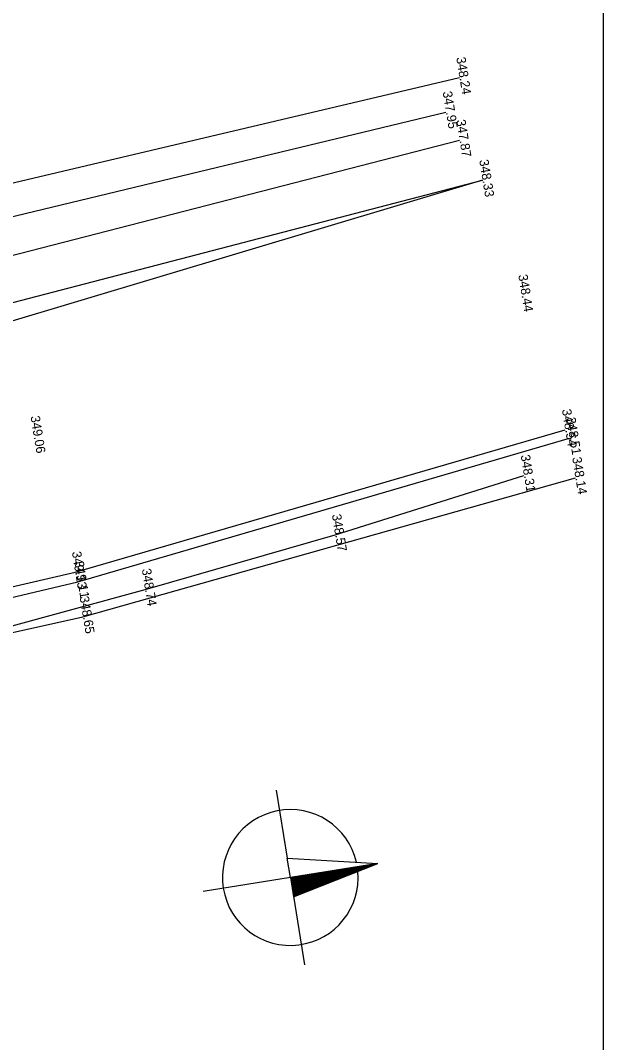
# Model space of a CAD drawing. Extents: x -600096 to -597522, y -1151695 to -1149849.
# Drawn here: x -599530.19 to -599518.4, y -1151599.7 to -1151579.02 of the extents above; entities that cross this region are included whole.
import ezdxf

# ---------------------------------------------------------------- set-up
doc = ezdxf.new("R2010")
doc.units = 0
for name, color, linetype in [('Hrana komunikace', 7, 'Continuous'), ('MPPV_Dno_prikopu', 7, 'Continuous'), ('MPPV_komunikace', 7, 'Continuous'), ('MPPV_svah', 7, 'Continuous'), ('Ram03', 7, 'Continuous'), ('rám', 7, 'Continuous'), ('Svodidla', 7, 'Continuous'), ('Tabulka', 7, 'Continuous'), ('Vrstva 12', 7, 'Continuous')]:
    doc.layers.add(name, color=color, linetype=linetype)

msp = doc.modelspace()

# ---------------------------------------------------------------- linework, layer by layer
at = {"layer": 'Hrana komunikace'}
for p, q in [((-599530.786, -1151584.848), (-599520.851, -1151582.258)), ((-599529.035, -1151590.381), (-599519.09, -1151587.475)), ((-599539.165, -1151592.769), (-599529.035, -1151590.381))]:
    msp.add_line(p, q, dxfattribs=at)
at = {"layer": 'MPPV_Dno_prikopu'}
for p, q in [((-599531.447, -1151583.253), (-599521.589, -1151580.878)), ((-599521.315, -1151581.452), (-599531.157, -1151583.986))]:
    msp.add_line(p, q, dxfattribs=at)
at = {"layer": 'MPPV_komunikace'}
for p, q in [((-599520.851, -1151582.258), (-599530.64, -1151585.189)), ((-599529.087, -1151590.186), (-599519.178, -1151587.307)), ((-599539.234, -1151592.527), (-599529.087, -1151590.186))]:
    msp.add_line(p, q, dxfattribs=at)
at = {"layer": 'MPPV_svah'}
for p, q in [((-599521.316, -1151580.186), (-599531.269, -1151582.536)), ((-599528.931, -1151591.093), (-599518.972, -1151588.277)), ((-599541.399, -1151593.867), (-599528.931, -1151591.093))]:
    msp.add_line(p, q, dxfattribs=at)
at = {"layer": 'Ram03'}
msp.add_line((-599518.403, -1151620.382), (-599518.403, -1151471.882), dxfattribs=at)
msp.add_line((-599518.403, -1151620.382), (-599518.403, -1151471.882), dxfattribs=at)
at = {"layer": 'rám'}
for p, q in [((-599523.557, -1151596.174), (-599523.55, -1151596.311)), ((-599523.552, -1151596.174), (-599523.545, -1151596.309)), ((-599523.547, -1151596.173), (-599523.54, -1151596.307)), ((-599523.542, -1151596.172), (-599523.536, -1151596.305)), ((-599523.537, -1151596.171), (-599523.531, -1151596.303)), ((-599523.532, -1151596.17), (-599523.526, -1151596.301)), ((-599523.527, -1151596.17), (-599523.521, -1151596.299)), ((-599523.522, -1151596.169), (-599523.516, -1151596.297)), ((-599523.517, -1151596.168), (-599523.511, -1151596.295)), ((-599523.512, -1151596.167), (-599523.506, -1151596.293)), ((-599523.507, -1151596.166), (-599523.501, -1151596.291)), ((-599523.502, -1151596.166), (-599523.496, -1151596.289)), ((-599523.497, -1151596.165), (-599523.491, -1151596.287)), ((-599523.492, -1151596.164), (-599523.486, -1151596.285)), ((-599523.487, -1151596.163), (-599523.482, -1151596.283)), ((-599523.482, -1151596.162), (-599523.477, -1151596.281)), ((-599523.477, -1151596.162), (-599523.472, -1151596.279)), ((-599523.472, -1151596.161), (-599523.467, -1151596.277)), ((-599523.467, -1151596.16), (-599523.462, -1151596.275)), ((-599523.462, -1151596.159), (-599523.457, -1151596.274)), ((-599523.457, -1151596.158), (-599523.452, -1151596.272)), ((-599523.452, -1151596.158), (-599523.447, -1151596.27)), ((-599523.447, -1151596.157), (-599523.442, -1151596.268)), ((-599523.442, -1151596.156), (-599523.437, -1151596.266)), ((-599523.437, -1151596.155), (-599523.432, -1151596.264)), ((-599523.432, -1151596.154), (-599523.427, -1151596.262)), ((-599523.428, -1151596.154), (-599523.423, -1151596.26)), ((-599523.423, -1151596.153), (-599523.418, -1151596.258)), ((-599523.418, -1151596.152), (-599523.413, -1151596.256)), ((-599523.413, -1151596.151), (-599523.408, -1151596.254)), ((-599523.408, -1151596.15), (-599523.403, -1151596.252)), ((-599523.403, -1151596.15), (-599523.398, -1151596.25)), ((-599523.398, -1151596.149), (-599523.393, -1151596.248)), ((-599523.393, -1151596.148), (-599523.388, -1151596.246)), ((-599523.388, -1151596.147), (-599523.383, -1151596.244)), ((-599523.383, -1151596.146), (-599523.378, -1151596.242)), ((-599523.378, -1151596.146), (-599523.373, -1151596.24)), ((-599523.373, -1151596.145), (-599523.368, -1151596.238)), ((-599523.368, -1151596.144), (-599523.364, -1151596.237)), ((-599523.363, -1151596.143), (-599523.359, -1151596.235)), ((-599523.358, -1151596.142), (-599523.354, -1151596.233)), ((-599523.353, -1151596.142), (-599523.349, -1151596.231)), ((-599523.348, -1151596.141), (-599523.344, -1151596.229)), ((-599523.343, -1151596.14), (-599523.339, -1151596.227)), ((-599523.338, -1151596.139), (-599523.334, -1151596.225)), ((-599523.333, -1151596.138), (-599523.329, -1151596.223)), ((-599523.328, -1151596.138), (-599523.324, -1151596.221)), ((-599523.323, -1151596.137), (-599523.319, -1151596.219)), ((-599523.318, -1151596.136), (-599523.314, -1151596.217)), ((-599523.313, -1151596.135), (-599523.31, -1151596.215)), ((-599523.308, -1151596.134), (-599523.305, -1151596.213)), ((-599523.303, -1151596.134), (-599523.3, -1151596.211)), ((-599523.298, -1151596.133), (-599523.295, -1151596.209)), ((-599523.293, -1151596.132), (-599523.29, -1151596.207)), ((-599523.288, -1151596.131), (-599523.285, -1151596.205)), ((-599523.283, -1151596.13), (-599523.28, -1151596.203)), ((-599523.278, -1151596.13), (-599523.275, -1151596.201)), ((-599523.274, -1151596.129), (-599523.27, -1151596.199)), ((-599523.269, -1151596.128), (-599523.265, -1151596.198)), ((-599523.264, -1151596.127), (-599523.26, -1151596.196)), ((-599523.259, -1151596.126), (-599523.255, -1151596.194)), ((-599523.254, -1151596.126), (-599523.251, -1151596.192)), ((-599523.249, -1151596.125), (-599523.246, -1151596.19)), ((-599523.244, -1151596.124), (-599523.241, -1151596.188)), ((-599523.239, -1151596.123), (-599523.236, -1151596.186)), ((-599523.234, -1151596.123), (-599523.231, -1151596.184)), ((-599523.229, -1151596.122), (-599523.226, -1151596.182)), ((-599523.224, -1151596.121), (-599523.221, -1151596.18)), ((-599523.219, -1151596.12), (-599523.216, -1151596.178)), ((-599523.214, -1151596.119), (-599523.211, -1151596.176)), ((-599523.209, -1151596.119), (-599523.206, -1151596.174)), ((-599523.204, -1151596.118), (-599523.201, -1151596.172)), ((-599523.199, -1151596.117), (-599523.196, -1151596.17)), ((-599523.194, -1151596.116), (-599523.192, -1151596.168)), ((-599523.189, -1151596.115), (-599523.187, -1151596.166)), ((-599523.184, -1151596.115), (-599523.182, -1151596.164)), ((-599523.179, -1151596.114), (-599523.177, -1151596.162)), ((-599523.174, -1151596.113), (-599523.172, -1151596.161)), ((-599523.169, -1151596.112), (-599523.167, -1151596.159)), ((-599523.164, -1151596.111), (-599523.162, -1151596.157)), ((-599523.159, -1151596.111), (-599523.157, -1151596.155)), ((-599523.154, -1151596.11), (-599523.152, -1151596.153)), ((-599523.149, -1151596.109), (-599523.147, -1151596.151)), ((-599523.144, -1151596.108), (-599523.142, -1151596.149)), ((-599523.139, -1151596.107), (-599523.138, -1151596.147)), ((-599523.134, -1151596.107), (-599523.133, -1151596.145)), ((-599523.129, -1151596.106), (-599523.128, -1151596.143)), ((-599523.124, -1151596.105), (-599523.123, -1151596.141)), ((-599523.12, -1151596.104), (-599523.118, -1151596.139)), ((-599523.115, -1151596.103), (-599523.113, -1151596.137)), ((-599523.11, -1151596.103), (-599523.108, -1151596.135)), ((-599523.105, -1151596.102), (-599523.103, -1151596.133)), ((-599523.1, -1151596.101), (-599523.098, -1151596.131)), ((-599523.095, -1151596.1), (-599523.093, -1151596.129)), ((-599523.09, -1151596.099), (-599523.088, -1151596.127)), ((-599523.085, -1151596.099), (-599523.083, -1151596.125)), ((-599523.08, -1151596.098), (-599523.079, -1151596.123)), ((-599523.075, -1151596.097), (-599523.074, -1151596.122)), ((-599523.07, -1151596.096), (-599523.069, -1151596.12)), ((-599523.065, -1151596.095), (-599523.064, -1151596.118)), ((-599523.06, -1151596.095), (-599523.059, -1151596.116)), ((-599523.055, -1151596.094), (-599523.054, -1151596.114)), ((-599523.05, -1151596.093), (-599523.049, -1151596.112)), ((-599523.045, -1151596.092), (-599523.044, -1151596.11)), ((-599523.04, -1151596.091), (-599523.039, -1151596.108)), ((-599523.035, -1151596.091), (-599523.034, -1151596.106)), ((-599523.03, -1151596.09), (-599523.029, -1151596.104)), ((-599523.025, -1151596.089), (-599523.025, -1151596.102)), ((-599523.02, -1151596.088), (-599523.02, -1151596.1)), ((-599523.015, -1151596.087), (-599523.015, -1151596.098)), ((-599523.01, -1151596.087), (-599523.01, -1151596.096)), ((-599523.005, -1151596.086), (-599523.005, -1151596.094)), ((-599523, -1151596.085), (-599523, -1151596.092)), ((-599522.995, -1151596.084), (-599522.995, -1151596.09)), ((-599522.99, -1151596.083), (-599522.99, -1151596.088)), ((-599522.985, -1151596.083), (-599522.985, -1151596.086)), ((-599522.98, -1151596.082), (-599522.98, -1151596.085)), ((-599522.975, -1151596.081), (-599522.975, -1151596.083)), ((-599522.97, -1151596.08), (-599522.97, -1151596.081)), ((-599524.734, -1151596.364), (-599524.734, -1151596.375)), ((-599524.729, -1151596.363), (-599524.727, -1151596.419)), ((-599524.724, -1151596.362), (-599524.719, -1151596.462)), ((-599524.719, -1151596.361), (-599524.712, -1151596.505)), ((-599524.714, -1151596.361), (-599524.705, -1151596.548)), ((-599524.709, -1151596.36), (-599524.698, -1151596.591)), ((-599524.704, -1151596.359), (-599524.691, -1151596.634)), ((-599524.699, -1151596.358), (-599524.684, -1151596.678)), ((-599524.694, -1151596.357), (-599524.677, -1151596.721)), ((-599524.689, -1151596.357), (-599524.671, -1151596.755)), ((-599524.684, -1151596.356), (-599524.666, -1151596.753)), ((-599524.679, -1151596.355), (-599524.661, -1151596.751)), ((-599524.674, -1151596.354), (-599524.656, -1151596.749)), ((-599524.67, -1151596.353), (-599524.651, -1151596.747)), ((-599524.665, -1151596.353), (-599524.646, -1151596.745)), ((-599524.66, -1151596.352), (-599524.641, -1151596.743)), ((-599524.655, -1151596.351), (-599524.636, -1151596.741)), ((-599524.65, -1151596.35), (-599524.631, -1151596.739)), ((-599524.645, -1151596.349), (-599524.626, -1151596.737)), ((-599524.64, -1151596.349), (-599524.622, -1151596.735)), ((-599524.635, -1151596.348), (-599524.617, -1151596.733)), ((-599524.63, -1151596.347), (-599524.612, -1151596.731)), ((-599524.625, -1151596.346), (-599524.607, -1151596.73)), ((-599524.62, -1151596.345), (-599524.602, -1151596.728)), ((-599524.615, -1151596.345), (-599524.597, -1151596.726)), ((-599524.61, -1151596.344), (-599524.592, -1151596.724)), ((-599524.605, -1151596.343), (-599524.587, -1151596.722)), ((-599524.6, -1151596.342), (-599524.582, -1151596.72)), ((-599524.595, -1151596.341), (-599524.577, -1151596.718)), ((-599524.59, -1151596.341), (-599524.572, -1151596.716)), ((-599524.585, -1151596.34), (-599524.568, -1151596.714)), ((-599524.58, -1151596.339), (-599524.563, -1151596.712)), ((-599524.575, -1151596.338), (-599524.558, -1151596.71)), ((-599524.57, -1151596.337), (-599524.553, -1151596.708)), ((-599524.565, -1151596.337), (-599524.548, -1151596.706)), ((-599524.56, -1151596.336), (-599524.543, -1151596.704)), ((-599524.555, -1151596.335), (-599524.538, -1151596.702)), ((-599524.55, -1151596.334), (-599524.533, -1151596.7)), ((-599524.545, -1151596.333), (-599524.528, -1151596.698)), ((-599524.54, -1151596.333), (-599524.523, -1151596.696)), ((-599524.535, -1151596.332), (-599524.518, -1151596.694)), ((-599524.53, -1151596.331), (-599524.513, -1151596.693)), ((-599524.525, -1151596.33), (-599524.509, -1151596.691)), ((-599524.52, -1151596.329), (-599524.504, -1151596.689)), ((-599524.516, -1151596.329), (-599524.499, -1151596.687)), ((-599524.511, -1151596.328), (-599524.494, -1151596.685)), ((-599524.506, -1151596.327), (-599524.489, -1151596.683)), ((-599524.501, -1151596.326), (-599524.484, -1151596.681)), ((-599524.496, -1151596.325), (-599524.479, -1151596.679)), ((-599524.491, -1151596.325), (-599524.474, -1151596.677)), ((-599524.486, -1151596.324), (-599524.469, -1151596.675)), ((-599524.481, -1151596.323), (-599524.464, -1151596.673)), ((-599524.476, -1151596.322), (-599524.459, -1151596.671)), ((-599524.471, -1151596.321), (-599524.454, -1151596.669)), ((-599524.466, -1151596.321), (-599524.45, -1151596.667)), ((-599524.461, -1151596.32), (-599524.445, -1151596.665)), ((-599524.456, -1151596.319), (-599524.44, -1151596.663)), ((-599524.451, -1151596.318), (-599524.435, -1151596.661)), ((-599524.446, -1151596.317), (-599524.43, -1151596.659)), ((-599524.441, -1151596.317), (-599524.425, -1151596.657)), ((-599524.436, -1151596.316), (-599524.42, -1151596.655)), ((-599524.431, -1151596.315), (-599524.415, -1151596.654)), ((-599524.426, -1151596.314), (-599524.41, -1151596.652)), ((-599524.421, -1151596.313), (-599524.405, -1151596.65)), ((-599524.416, -1151596.313), (-599524.4, -1151596.648)), ((-599524.411, -1151596.312), (-599524.396, -1151596.646)), ((-599524.406, -1151596.311), (-599524.391, -1151596.644)), ((-599524.401, -1151596.31), (-599524.386, -1151596.642)), ((-599524.396, -1151596.309), (-599524.381, -1151596.64)), ((-599524.391, -1151596.309), (-599524.376, -1151596.638)), ((-599524.386, -1151596.308), (-599524.371, -1151596.636)), ((-599524.381, -1151596.307), (-599524.366, -1151596.634)), ((-599524.376, -1151596.306), (-599524.361, -1151596.632)), ((-599524.371, -1151596.305), (-599524.356, -1151596.63)), ((-599524.366, -1151596.305), (-599524.351, -1151596.628)), ((-599524.362, -1151596.304), (-599524.346, -1151596.626)), ((-599524.357, -1151596.303), (-599524.341, -1151596.624)), ((-599524.352, -1151596.302), (-599524.337, -1151596.622)), ((-599524.347, -1151596.301), (-599524.332, -1151596.62)), ((-599524.342, -1151596.301), (-599524.327, -1151596.618)), ((-599524.337, -1151596.3), (-599524.322, -1151596.617)), ((-599524.332, -1151596.299), (-599524.317, -1151596.615)), ((-599524.327, -1151596.298), (-599524.312, -1151596.613)), ((-599524.322, -1151596.297), (-599524.307, -1151596.611)), ((-599524.317, -1151596.297), (-599524.302, -1151596.609)), ((-599524.312, -1151596.296), (-599524.297, -1151596.607)), ((-599524.307, -1151596.295), (-599524.292, -1151596.605)), ((-599524.302, -1151596.294), (-599524.287, -1151596.603)), ((-599524.297, -1151596.293), (-599524.282, -1151596.601)), ((-599524.292, -1151596.293), (-599524.278, -1151596.599)), ((-599524.287, -1151596.292), (-599524.273, -1151596.597)), ((-599524.282, -1151596.291), (-599524.268, -1151596.595)), ((-599524.277, -1151596.29), (-599524.263, -1151596.593)), ((-599524.272, -1151596.289), (-599524.258, -1151596.591)), ((-599524.267, -1151596.289), (-599524.253, -1151596.589)), ((-599524.262, -1151596.288), (-599524.248, -1151596.587)), ((-599524.257, -1151596.287), (-599524.243, -1151596.585)), ((-599524.252, -1151596.286), (-599524.238, -1151596.583)), ((-599524.247, -1151596.285), (-599524.233, -1151596.581)), ((-599524.242, -1151596.285), (-599524.228, -1151596.579)), ((-599524.237, -1151596.284), (-599524.224, -1151596.578)), ((-599524.232, -1151596.283), (-599524.219, -1151596.576)), ((-599524.227, -1151596.282), (-599524.214, -1151596.574)), ((-599524.222, -1151596.281), (-599524.209, -1151596.572)), ((-599524.217, -1151596.281), (-599524.204, -1151596.57)), ((-599524.212, -1151596.28), (-599524.199, -1151596.568)), ((-599524.208, -1151596.279), (-599524.194, -1151596.566)), ((-599524.203, -1151596.278), (-599524.189, -1151596.564)), ((-599524.198, -1151596.277), (-599524.184, -1151596.562)), ((-599524.193, -1151596.277), (-599524.179, -1151596.56)), ((-599524.188, -1151596.276), (-599524.174, -1151596.558)), ((-599524.183, -1151596.275), (-599524.169, -1151596.556)), ((-599524.178, -1151596.274), (-599524.165, -1151596.554)), ((-599524.173, -1151596.273), (-599524.16, -1151596.552)), ((-599524.168, -1151596.273), (-599524.155, -1151596.55)), ((-599524.163, -1151596.272), (-599524.15, -1151596.548)), ((-599524.158, -1151596.271), (-599524.145, -1151596.546)), ((-599524.153, -1151596.27), (-599524.14, -1151596.544)), ((-599524.148, -1151596.269), (-599524.135, -1151596.542)), ((-599524.143, -1151596.269), (-599524.13, -1151596.541)), ((-599524.138, -1151596.268), (-599524.125, -1151596.539)), ((-599524.133, -1151596.267), (-599524.12, -1151596.537)), ((-599524.128, -1151596.266), (-599524.115, -1151596.535)), ((-599524.123, -1151596.265), (-599524.11, -1151596.533)), ((-599524.118, -1151596.265), (-599524.106, -1151596.531)), ((-599524.113, -1151596.264), (-599524.101, -1151596.529)), ((-599524.108, -1151596.263), (-599524.096, -1151596.527)), ((-599524.103, -1151596.262), (-599524.091, -1151596.525)), ((-599524.098, -1151596.261), (-599524.086, -1151596.523)), ((-599524.093, -1151596.261), (-599524.081, -1151596.521)), ((-599524.088, -1151596.26), (-599524.076, -1151596.519)), ((-599524.083, -1151596.259), (-599524.071, -1151596.517)), ((-599524.078, -1151596.258), (-599524.066, -1151596.515)), ((-599524.073, -1151596.257), (-599524.061, -1151596.513)), ((-599524.068, -1151596.257), (-599524.056, -1151596.511)), ((-599524.063, -1151596.256), (-599524.052, -1151596.509)), ((-599524.058, -1151596.255), (-599524.047, -1151596.507)), ((-599524.053, -1151596.254), (-599524.042, -1151596.505)), ((-599524.049, -1151596.253), (-599524.037, -1151596.503)), ((-599524.044, -1151596.253), (-599524.032, -1151596.502)), ((-599524.039, -1151596.252), (-599524.027, -1151596.5)), ((-599524.034, -1151596.251), (-599524.022, -1151596.498)), ((-599524.029, -1151596.25), (-599524.017, -1151596.496)), ((-599524.024, -1151596.249), (-599524.012, -1151596.494)), ((-599524.019, -1151596.249), (-599524.007, -1151596.492)), ((-599524.014, -1151596.248), (-599524.002, -1151596.49)), ((-599524.009, -1151596.247), (-599523.997, -1151596.488)), ((-599524.004, -1151596.246), (-599523.993, -1151596.486)), ((-599523.999, -1151596.246), (-599523.988, -1151596.484)), ((-599523.994, -1151596.245), (-599523.983, -1151596.482)), ((-599523.989, -1151596.244), (-599523.978, -1151596.48)), ((-599523.984, -1151596.243), (-599523.973, -1151596.478)), ((-599523.979, -1151596.242), (-599523.968, -1151596.476)), ((-599523.974, -1151596.242), (-599523.963, -1151596.474)), ((-599523.969, -1151596.241), (-599523.958, -1151596.472)), ((-599523.964, -1151596.24), (-599523.953, -1151596.47)), ((-599523.959, -1151596.239), (-599523.948, -1151596.468)), ((-599523.954, -1151596.238), (-599523.943, -1151596.466)), ((-599523.949, -1151596.238), (-599523.939, -1151596.465)), ((-599523.944, -1151596.237), (-599523.934, -1151596.463)), ((-599523.939, -1151596.236), (-599523.929, -1151596.461)), ((-599523.934, -1151596.235), (-599523.924, -1151596.459)), ((-599523.929, -1151596.234), (-599523.919, -1151596.457)), ((-599523.924, -1151596.234), (-599523.914, -1151596.455)), ((-599523.919, -1151596.233), (-599523.909, -1151596.453)), ((-599523.914, -1151596.232), (-599523.904, -1151596.451)), ((-599523.909, -1151596.231), (-599523.899, -1151596.449)), ((-599523.904, -1151596.23), (-599523.894, -1151596.447)), ((-599523.899, -1151596.23), (-599523.889, -1151596.445)), ((-599523.895, -1151596.229), (-599523.884, -1151596.443)), ((-599523.89, -1151596.228), (-599523.88, -1151596.441)), ((-599523.885, -1151596.227), (-599523.875, -1151596.439)), ((-599523.88, -1151596.226), (-599523.87, -1151596.437)), ((-599523.875, -1151596.226), (-599523.865, -1151596.435)), ((-599523.87, -1151596.225), (-599523.86, -1151596.433)), ((-599523.865, -1151596.224), (-599523.855, -1151596.431)), ((-599523.86, -1151596.223), (-599523.85, -1151596.429)), ((-599523.855, -1151596.222), (-599523.845, -1151596.427)), ((-599523.85, -1151596.222), (-599523.84, -1151596.426)), ((-599523.845, -1151596.221), (-599523.835, -1151596.424)), ((-599523.84, -1151596.22), (-599523.83, -1151596.422)), ((-599523.835, -1151596.219), (-599523.825, -1151596.42)), ((-599523.83, -1151596.218), (-599523.821, -1151596.418)), ((-599523.825, -1151596.218), (-599523.816, -1151596.416)), ((-599523.82, -1151596.217), (-599523.811, -1151596.414)), ((-599523.815, -1151596.216), (-599523.806, -1151596.412)), ((-599523.81, -1151596.215), (-599523.801, -1151596.41)), ((-599523.805, -1151596.214), (-599523.796, -1151596.408)), ((-599523.8, -1151596.214), (-599523.791, -1151596.406)), ((-599523.795, -1151596.213), (-599523.786, -1151596.404)), ((-599523.79, -1151596.212), (-599523.781, -1151596.402)), ((-599523.785, -1151596.211), (-599523.776, -1151596.4)), ((-599523.78, -1151596.21), (-599523.771, -1151596.398)), ((-599523.775, -1151596.21), (-599523.767, -1151596.396)), ((-599523.77, -1151596.209), (-599523.762, -1151596.394)), ((-599523.765, -1151596.208), (-599523.757, -1151596.392)), ((-599523.76, -1151596.207), (-599523.752, -1151596.39)), ((-599523.755, -1151596.206), (-599523.747, -1151596.389)), ((-599523.75, -1151596.206), (-599523.742, -1151596.387)), ((-599523.745, -1151596.205), (-599523.737, -1151596.385)), ((-599523.741, -1151596.204), (-599523.732, -1151596.383)), ((-599523.736, -1151596.203), (-599523.727, -1151596.381)), ((-599523.731, -1151596.202), (-599523.722, -1151596.379)), ((-599523.726, -1151596.202), (-599523.717, -1151596.377)), ((-599523.721, -1151596.201), (-599523.712, -1151596.375)), ((-599523.716, -1151596.2), (-599523.708, -1151596.373)), ((-599523.711, -1151596.199), (-599523.703, -1151596.371)), ((-599523.706, -1151596.198), (-599523.698, -1151596.369)), ((-599523.701, -1151596.198), (-599523.693, -1151596.367)), ((-599523.696, -1151596.197), (-599523.688, -1151596.365)), ((-599523.691, -1151596.196), (-599523.683, -1151596.363)), ((-599523.686, -1151596.195), (-599523.678, -1151596.361)), ((-599523.681, -1151596.194), (-599523.673, -1151596.359)), ((-599523.676, -1151596.194), (-599523.668, -1151596.357)), ((-599523.671, -1151596.193), (-599523.663, -1151596.355)), ((-599523.666, -1151596.192), (-599523.658, -1151596.353)), ((-599523.661, -1151596.191), (-599523.653, -1151596.351)), ((-599523.656, -1151596.19), (-599523.649, -1151596.35)), ((-599523.651, -1151596.19), (-599523.644, -1151596.348)), ((-599523.646, -1151596.189), (-599523.639, -1151596.346)), ((-599523.641, -1151596.188), (-599523.634, -1151596.344)), ((-599523.636, -1151596.187), (-599523.629, -1151596.342)), ((-599523.631, -1151596.186), (-599523.624, -1151596.34)), ((-599523.626, -1151596.186), (-599523.619, -1151596.338)), ((-599523.621, -1151596.185), (-599523.614, -1151596.336)), ((-599523.616, -1151596.184), (-599523.609, -1151596.334)), ((-599523.611, -1151596.183), (-599523.604, -1151596.332)), ((-599523.606, -1151596.182), (-599523.599, -1151596.33)), ((-599523.601, -1151596.182), (-599523.595, -1151596.328)), ((-599523.596, -1151596.181), (-599523.59, -1151596.326)), ((-599523.591, -1151596.18), (-599523.585, -1151596.324)), ((-599523.587, -1151596.179), (-599523.58, -1151596.322)), ((-599523.582, -1151596.178), (-599523.575, -1151596.32)), ((-599523.577, -1151596.178), (-599523.57, -1151596.318)), ((-599523.572, -1151596.177), (-599523.565, -1151596.316)), ((-599523.567, -1151596.176), (-599523.56, -1151596.314)), ((-599523.562, -1151596.175), (-599523.555, -1151596.313))]:
    msp.add_line(p, q, dxfattribs=at)
at = {"layer": 'Svodidla'}
for p, q in [((-599523.83, -1151589.432), (-599520.012, -1151588.231)), ((-599527.673, -1151590.536), (-599523.83, -1151589.432)), ((-599531.612, -1151591.615), (-599527.673, -1151590.536))]:
    msp.add_line(p, q, dxfattribs=at)
at = {"layer": 'Tabulka'}
for p, q in [((-599525.02, -1151594.598), (-599524.798, -1151595.972)), ((-599524.735, -1151596.364), (-599524.798, -1151595.972)), ((-599524.798, -1151595.972), (-599522.969, -1151596.08)), ((-599522.969, -1151596.08), (-599524.735, -1151596.364)), ((-599522.969, -1151596.08), (-599524.735, -1151596.364)), ((-599524.672, -1151596.755), (-599522.969, -1151596.08)), ((-599524.735, -1151596.364), (-599526.501, -1151596.648)), ((-599524.735, -1151596.364), (-599524.45, -1151598.13)), ((-599524.735, -1151596.364), (-599524.672, -1151596.755))]:
    msp.add_line(p, q, dxfattribs=at)
msp.add_arc((-599524.735, -1151596.364), 1.373, 13.0459, 5.2819, dxfattribs=at)

# ---------------------------------------------------------------- texts
at = {"layer": 'Vrstva 12'}
for s, p in [('348.24 ', (-599521.381, -1151579.778)), ('347.95 ', (-599521.655, -1151580.47)), ('347.87 ', (-599521.38, -1151581.044)), ('348.33 ', (-599520.916, -1151581.851)), ('348.44 ', (-599520.127, -1151584.175)), ('349.06 ', (-599529.988, -1151587.036)), ('348.54 ', (-599519.244, -1151586.899)), ('348.51 ', (-599519.156, -1151587.067)), ('348.31 ', (-599520.078, -1151587.823)), ('348.14 ', (-599519.037, -1151587.869)), ('348.57 ', (-599523.895, -1151589.024)), ('349.13 ', (-599529.152, -1151589.778)), ('349.11 ', (-599529.101, -1151589.973)), ('348.74 ', (-599527.739, -1151590.128)), ('348.65 ', (-599528.996, -1151590.685))]:
    msp.add_text(s, height=0.1875, rotation=279.1328, dxfattribs=at).set_placement(p)

doc.saveas('drawing.dxf')
